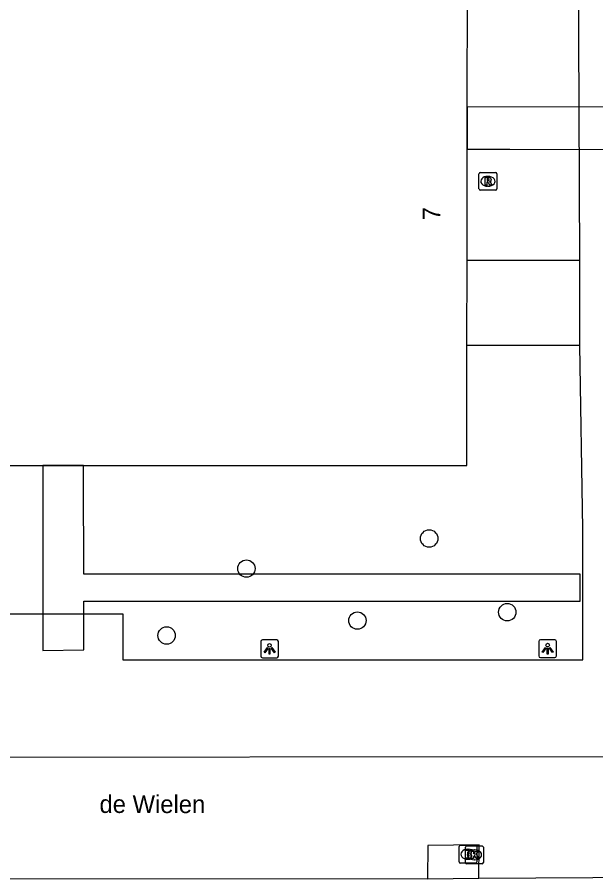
# Model space of a CAD drawing. Extents: x 161477 to 163040, y 383680 to 384868.
# Drawn here: x 162057.1 to 162089.64, y 384190.88 to 384239.31 of the extents above; entities that cross this region are included whole.
import ezdxf

# ---------------------------------------------------------------- set-up
doc = ezdxf.new("R2010")
doc.units = 0
for name, color, linetype in [('IMGEO_Boom', 7, 'Continuous'), ('IMGEO_Brandkraan', 7, 'Continuous'), ('IMGEO_Dek', 7, 'Continuous'), ('IMGEO_Kolk', 7, 'Continuous'), ('IMGEO_Lichtpunt', 7, 'Continuous'), ('IMGEO_Openbare_ruimte_label', 7, 'Continuous'), ('IMGEO_Pand', 7, 'Continuous'), ('IMGEO_Pand_nummerreeks', 7, 'Continuous'), ('IMGEO_Rioolput', 7, 'Continuous'), ('IMGEO_Voetpad_gesloten', 7, 'Continuous'), ('IMGEO_Voetpad_open', 7, 'Continuous')]:
    doc.layers.add(name, color=color, linetype=linetype)

msp = doc.modelspace()

# ---------------------------------------------------------------- linework, layer by layer
at = {"layer": 'IMGEO_Boom'}
for centre in [(162080.266, 384210.009), (162069.988, 384208.318), (162084.657, 384205.867), (162076.23, 384205.395), (162065.5, 384204.556)]:
    msp.add_circle(centre, 0.489, dxfattribs=at)
at = {"layer": 'IMGEO_Brandkraan'}
for p, q in [((162081.949, 384191.834), (162081.949, 384192.686)), ((162082.024, 384192.76), (162082.876, 384192.76)), ((162082.95, 384192.686), (162082.95, 384191.834)), ((162082.437, 384192.54), (162082.462, 384192.54)), ((162082.876, 384191.76), (162082.024, 384191.76)), ((162082.46, 384191.98), (162082.435, 384191.98))]:
    msp.add_line(p, q, dxfattribs=at)
for points in [[(162081.949, 384191.834), (162081.949, 384192.686)], [(162082.024, 384192.76), (162082.876, 384192.76)], [(162082.95, 384192.686), (162082.95, 384191.834)], [(162082.297, 384192.46), (162082.297, 384192.06), (162082.51, 384192.06)], [(162082.528, 384192.46), (162082.297, 384192.46)], [(162082.476, 384192.379), (162082.422, 384192.379), (162082.422, 384192.303)], [(162082.422, 384192.303), (162082.475, 384192.303)], [(162082.484, 384192.227), (162082.422, 384192.227), (162082.422, 384192.146)], [(162082.422, 384192.146), (162082.484, 384192.146)], [(162082.876, 384191.76), (162082.024, 384191.76)]]:
    msp.add_lwpolyline(points, dxfattribs=at)
for centre, radius, start, end in [((162082.026, 384192.684), 0.0765, 91.552, 178.448), ((162082.026, 384192.684), 0.0765, 91.552, 178.448), ((162082.874, 384192.684), 0.0765, 1.552, 88.448), ((162082.874, 384192.684), 0.0765, 1.552, 88.448), ((162082.477, 384192.341), 0.0379, 267.8285, 90.9355), ((162082.485, 384192.186), 0.0404, 269.8759, 90.5077), ((162082.516, 384192.311), 0.251, 268.6676, 293.5347), ((162082.532, 384192.315), 0.145, 59.4692, 91.5367), ((162082.557, 384192.362), 0.0922, 285.5137, 58.1501), ((162082.562, 384192.17), 0.105, 301.3115, 78.989), ((162082.026, 384191.836), 0.0765, 181.552, 268.448), ((162082.026, 384191.836), 0.0765, 181.552, 268.448), ((162082.874, 384191.836), 0.0765, 271.552, 358.448), ((162082.874, 384191.836), 0.0765, 271.552, 358.448)]:
    msp.add_arc(centre, radius, start, end, dxfattribs=at)
for centre, major_axis, ratio, start_param, end_param in [((162082.436, 384192.26), (-0.387, 0.002), 0.722429, 4.712389, 7.853982), ((162082.461, 384192.26), (-0.39, 0.002), 0.717154, 1.570796, 4.712389)]:
    msp.add_ellipse(centre, major_axis=major_axis, ratio=ratio, start_param=start_param, end_param=end_param, dxfattribs=at)
at = {"layer": 'IMGEO_Dek'}
for points in [[(162092.103, 384234.259), (162082.412, 384234.268), (162082.408, 384231.898), (162082.675, 384231.897), (162084.062, 384231.895), (162084.808, 384231.893), (162092.092, 384231.879), (162095.665, 384231.872), (162095.679, 384231.511), (162097.235, 384229.958), (162098.908, 384229.957), (162100.304, 384229.957), (162100.65, 384230.291), (162101.179, 384230.802), (162101.856, 384231.456), (162101.862, 384232.56), (162101.872, 384234.603), (162100.349, 384236.153), (162097.23, 384236.159), (162095.672, 384234.611), (162095.673, 384234.256)], [(162088.766, 384207.998), (162060.844, 384207.998), (162060.83, 384213.42), (162060.829, 384214.111), (162058.542, 384214.112), (162058.543, 384213.413), (162058.545, 384205.795), (162058.545, 384203.721), (162060.837, 384203.743), (162060.841, 384205.834), (162060.849, 384206.487), (162088.767, 384206.48)]]:
    msp.add_lwpolyline(points, close=True, dxfattribs=at)
at = {"layer": 'IMGEO_Kolk'}
for p, q in [((162082.313, 384191.799), (162082.313, 384192.651)), ((162082.388, 384192.725), (162083.24, 384192.725)), ((162083.314, 384192.651), (162083.314, 384191.799)), ((162082.801, 384192.505), (162082.826, 384192.505)), ((162083.24, 384191.725), (162082.388, 384191.725)), ((162082.824, 384191.945), (162082.799, 384191.945))]:
    msp.add_line(p, q, dxfattribs=at)
for points in [[(162082.313, 384191.799), (162082.313, 384192.651)], [(162082.388, 384192.725), (162083.24, 384192.725)], [(162083.314, 384192.651), (162083.314, 384191.799)], [(162082.634, 384192.425), (162082.757, 384192.425), (162082.757, 384192.274), (162082.887, 384192.425), (162083.051, 384192.425), (162082.905, 384192.274), (162083.058, 384192.025), (162082.906, 384192.025), (162082.821, 384192.189), (162082.757, 384192.122), (162082.757, 384192.025), (162082.634, 384192.025), (162082.634, 384192.425)], [(162083.24, 384191.725), (162082.388, 384191.725)]]:
    msp.add_lwpolyline(points, dxfattribs=at)
for centre, start, end in [((162082.39, 384192.649), 91.552, 178.448), ((162082.39, 384192.649), 91.552, 178.448), ((162083.238, 384192.649), 1.552, 88.448), ((162083.238, 384192.649), 1.552, 88.448), ((162082.39, 384191.801), 181.552, 268.448), ((162082.39, 384191.801), 181.552, 268.448), ((162083.238, 384191.801), 271.552, 358.448), ((162083.238, 384191.801), 271.552, 358.448)]:
    msp.add_arc(centre, 0.0765, start, end, dxfattribs=at)
for centre, major_axis, ratio, start_param, end_param in [((162082.8, 384192.225), (-0.387, 0.002), 0.722429, 4.712389, 7.853982), ((162082.825, 384192.225), (-0.39, 0.002), 0.717154, 1.570796, 4.712389)]:
    msp.add_ellipse(centre, major_axis=major_axis, ratio=ratio, start_param=start_param, end_param=end_param, dxfattribs=at)
at = {"layer": 'IMGEO_Lichtpunt'}
for p, q in [((162070.79, 384204.21), (162070.79, 384203.403)), ((162070.79, 384204.21), (162070.79, 384203.403)), ((162071.692, 384204.305), (162070.884, 384204.305)), ((162071.692, 384204.305), (162070.884, 384204.305)), ((162071.786, 384203.403), (162071.786, 384204.21)), ((162071.786, 384203.403), (162071.786, 384204.21)), ((162086.428, 384204.219), (162086.428, 384203.412)), ((162086.428, 384204.219), (162086.428, 384203.412)), ((162087.33, 384204.314), (162086.522, 384204.314)), ((162087.33, 384204.314), (162086.522, 384204.314)), ((162087.424, 384203.412), (162087.424, 384204.219)), ((162087.424, 384203.412), (162087.424, 384204.219)), ((162070.884, 384203.309), (162071.692, 384203.309)), ((162070.884, 384203.309), (162071.692, 384203.309)), ((162086.522, 384203.318), (162087.33, 384203.318)), ((162086.522, 384203.318), (162087.33, 384203.318))]:
    msp.add_line(p, q, dxfattribs=at)
for points in [[(162071.164, 384203.874), (162071.203, 384203.846), (162071.015, 384203.584), (162070.977, 384203.611), (162071.164, 384203.874)], [(162071.266, 384203.826), (162071.313, 384203.826), (162071.313, 384203.504), (162071.266, 384203.504), (162071.266, 384203.826)], [(162071.376, 384203.846), (162071.414, 384203.873), (162071.601, 384203.611), (162071.562, 384203.583), (162071.376, 384203.846)], [(162086.802, 384203.883), (162086.841, 384203.855), (162086.653, 384203.593), (162086.615, 384203.62), (162086.802, 384203.883)], [(162086.904, 384203.835), (162086.951, 384203.835), (162086.951, 384203.513), (162086.904, 384203.513), (162086.904, 384203.835)], [(162087.014, 384203.855), (162087.052, 384203.882), (162087.239, 384203.62), (162087.2, 384203.592), (162087.014, 384203.855)]]:
    msp.add_lwpolyline(points, dxfattribs=at)
for centre in [(162071.289, 384204.008), (162086.927, 384204.017)]:
    msp.add_circle(centre, 0.0994, dxfattribs=at)
for centre, start, end in [((162070.884, 384204.21), 90, 180), ((162070.884, 384204.21), 90, 180), ((162071.692, 384204.21), 0, 90), ((162071.692, 384204.21), 0, 90), ((162086.522, 384204.219), 90, 180), ((162086.522, 384204.219), 90, 180), ((162087.33, 384204.219), 0, 90), ((162087.33, 384204.219), 0, 90), ((162070.884, 384203.403), 180, 270), ((162070.884, 384203.403), 180, 270), ((162071.692, 384203.403), 270, 0), ((162071.692, 384203.403), 270, 360), ((162086.522, 384203.412), 180, 270), ((162086.522, 384203.412), 180, 270), ((162087.33, 384203.412), 270, 0), ((162087.33, 384203.412), 270, 360)]:
    msp.add_arc(centre, 0.0946, start, end, dxfattribs=at)
at = {"layer": 'IMGEO_Pand'}
for points in [[(162082.399, 384225.651), (162082.408, 384231.898), (162082.412, 384234.268), (162082.422, 384240.901), (162061.823, 384240.891), (162060.867, 384240.892), (162058.494, 384240.893), (162057.612, 384240.894), (162036.997, 384240.896), (162036.996, 384234.345), (162036.996, 384231.857), (162036.996, 384231.817), (162036.996, 384228.133), (162037.096, 384226.903)], [(162082.385, 384220.86), (162082.399, 384225.651)], [(162054.752, 384214.113), (162082.389, 384214.105), (162082.384, 384220.627), (162082.385, 384220.86)]]:
    msp.add_lwpolyline(points, dxfattribs=at)
at = {"layer": 'IMGEO_Rioolput'}
for p, q in [((162083.069, 384229.664), (162083.069, 384230.516)), ((162083.144, 384230.59), (162083.996, 384230.59)), ((162083.557, 384230.37), (162083.582, 384230.37)), ((162084.07, 384230.516), (162084.07, 384229.664)), ((162083.996, 384229.59), (162083.144, 384229.59)), ((162083.58, 384229.81), (162083.555, 384229.81))]:
    msp.add_line(p, q, dxfattribs=at)
for points in [[(162083.069, 384229.664), (162083.069, 384230.516)], [(162083.144, 384230.59), (162083.996, 384230.59)], [(162084.07, 384230.516), (162084.07, 384229.664)], [(162083.658, 384230.288), (162083.406, 384230.29), (162083.406, 384229.89)], [(162083.406, 384229.89), (162083.53, 384229.89), (162083.53, 384230.052), (162083.541, 384230.052)], [(162083.584, 384230.209), (162083.53, 384230.209), (162083.53, 384230.128)], [(162083.53, 384230.128), (162083.582, 384230.128)], [(162083.588, 384230.023), (162083.659, 384229.89), (162083.799, 384229.89), (162083.734, 384230.016)], [(162083.996, 384229.59), (162083.144, 384229.59)]]:
    msp.add_lwpolyline(points, dxfattribs=at)
for centre, radius, start, end in [((162083.146, 384230.514), 0.0765, 91.552, 178.448), ((162083.146, 384230.514), 0.0765, 91.552, 178.448), ((162083.994, 384230.514), 0.0765, 1.552, 88.448), ((162083.994, 384230.514), 0.0765, 1.552, 88.448), ((162083.54, 384229.999), 0.0533, 26.0293, 88.6989), ((162083.566, 384230.317), 0.19, 274.7715, 282.9687), ((162083.59, 384230.113), 0.0964, 77.0061, 93.1865), ((162083.604, 384230.17), 0.0378, 276.6634, 79.6772), ((162083.657, 384230.178), 0.109, 350.3612, 89.416), ((162083.655, 384230.178), 0.112, 277.5842, 350.9817), ((162083.639, 384229.963), 0.108, 29.5134, 73.7905), ((162083.146, 384229.666), 0.0765, 181.552, 268.448), ((162083.146, 384229.666), 0.0765, 181.552, 268.448), ((162083.994, 384229.666), 0.0765, 271.552, 358.448), ((162083.994, 384229.666), 0.0765, 271.552, 358.448)]:
    msp.add_arc(centre, radius, start, end, dxfattribs=at)
for centre, major_axis, ratio, start_param, end_param in [((162083.556, 384230.09), (-0.387, 0.002), 0.722429, 4.712389, 7.853982), ((162083.581, 384230.09), (-0.39, 0.002), 0.717154, 1.570796, 4.712389)]:
    msp.add_ellipse(centre, major_axis=major_axis, ratio=ratio, start_param=start_param, end_param=end_param, dxfattribs=at)
at = {"layer": 'IMGEO_Voetpad_gesloten'}
for points in [[(162101.872, 384234.603), (162100.349, 384236.153), (162097.23, 384236.159), (162095.672, 384234.611), (162095.673, 384234.256), (162092.103, 384234.259), (162082.412, 384234.268), (162082.408, 384231.898), (162082.675, 384231.897), (162084.062, 384231.895), (162084.808, 384231.893), (162092.092, 384231.879), (162095.665, 384231.872), (162095.679, 384231.511), (162097.235, 384229.958), (162098.908, 384229.957), (162100.304, 384229.957), (162100.65, 384230.291), (162101.179, 384230.802), (162101.856, 384231.456), (162101.862, 384232.56), (162101.872, 384234.603)], [(162088.766, 384207.998), (162060.844, 384207.998), (162060.83, 384213.42), (162060.829, 384214.111), (162058.542, 384214.112), (162058.543, 384213.413), (162058.545, 384205.795), (162058.545, 384203.721), (162060.837, 384203.743), (162060.841, 384205.834), (162060.849, 384206.487), (162088.767, 384206.48), (162088.766, 384207.998)]]:
    msp.add_lwpolyline(points, dxfattribs=at)
at = {"layer": 'IMGEO_Voetpad_open'}
for points in [[(162088.744, 384225.652), (162088.671, 384242.578), (162079.599, 384242.59), (162035.635, 384242.572), (162035.61, 384234.345), (162035.617, 384231.857), (162035.674, 384210.817), (162035.689, 384205.774), (162036.977, 384205.775), (162039.977, 384205.776), (162041.587, 384205.777)], [(162041.924, 384190.961), (162041.937, 384197.345), (162041.938, 384197.717), (162098.373, 384197.75), (162098.374, 384205.812), (162106.811, 384205.822), (162106.921, 384228.996)], [(162082.399, 384225.651), (162088.744, 384225.652)], [(162088.75, 384220.868), (162088.744, 384225.652)], [(162052.966, 384205.769), (162063.039, 384205.769), (162063.039, 384203.191), (162088.916, 384203.191), (162088.916, 384210.562), (162088.75, 384220.868)], [(162088.75, 384220.868), (162084.75, 384220.863), (162082.385, 384220.86)], [(162083.053, 384190.907), (162083.082, 384192.779), (162080.195, 384192.756), (162080.169, 384190.88)], [(162041.924, 384190.961), (162056.233, 384190.888), (162080.169, 384190.88)], [(162080.169, 384190.88), (162083.053, 384190.907)], [(162083.053, 384190.907), (162102.274, 384191.019)]]:
    msp.add_lwpolyline(points, dxfattribs=at)

# ---------------------------------------------------------------- texts
at = {"layer": 'IMGEO_Openbare_ruimte_label'}
msp.add_text('de Wielen', height=1, rotation=359.8854, dxfattribs=at).set_placement((162061.724, 384194.581))
at = {"layer": 'IMGEO_Pand_nummerreeks'}
msp.add_text('7', height=1, rotation=89.92, dxfattribs=at).set_placement((162080.903, 384227.898))

doc.saveas('drawing.dxf')
